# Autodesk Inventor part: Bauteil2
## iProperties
Created: 2005-12
Part Number: Bauteil2
Document SubType Name: Modeling
Designer: mp
Author: mp
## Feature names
1. Drehung1 [Revolution]
2. Extrusion1
3. Rundung1 [Fillet]
4. Runde Anordnung1 [Circular Pattern]
5. Sweeping1
6. Rundung2 [Fillet]
7. Runde Anordnung2 [Circular Pattern]
